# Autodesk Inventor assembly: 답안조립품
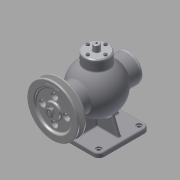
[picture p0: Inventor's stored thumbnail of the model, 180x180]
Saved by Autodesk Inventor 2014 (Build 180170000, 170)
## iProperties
Created: 2015-10
Part Number: 답안조립품
Document SubType Name: Assembly
Designer: youjin13
Author: youjin13
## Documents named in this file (19)
- C:\Users\youjin13\Desktop\451010V1009\답안조립품.iam
- C:\Users\youjin13\Desktop\451010V1009\본체.ipt
- C:\Users\youjin13\Desktop\451010V1009\뒤커버.ipt
- C:\Users\youjin13\Desktop\451010V1009\앞커버.ipt
- C:\Users\youjin13\Desktop\451010V1009\상부커버.ipt
- C:\Users\youjin13\Desktop\451010V1009\오일실 15 30 7.ipt
- C:\Users\youjin13\Desktop\451010V1009\볼트 M4 x 16.ipt
- C:\Users\youjin13\Desktop\451010V1009\볼트 M 4 x 12.ipt
- C:\Users\youjin13\Desktop\451010V1009\베어링- 6202.ipt
- KS B 2023 - 6202 - 15 x 35 x 11 - 7.8.ipt
- C:\Users\youjin13\Desktop\451010V1009\편심축.ipt
- C:\Users\youjin13\Desktop\451010V1009\부시.ipt
- C:\Users\youjin13\Desktop\451010V1009\키 4 x 4 x 12.ipt
- C:\Users\youjin13\Desktop\451010V1009\멈춤링- 35x1.6.ipt
- KS B 1336 - 35x1.6.ipt
- C:\Users\youjin13\Desktop\451010V1009\멈춤링- 15 x 1.ipt
- C:\Users\youjin13\Desktop\451010V1009\V-벨트풀리.ipt
- C:\Users\youjin13\Desktop\451010V1009\너트 M8.ipt
- C:\Users\youjin13\Desktop\451010V1009\슬라이드.ipt
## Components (16 placed, 5 different names)
1. KS B 2023 - 6202 - 15 x 35 x 11 - 7.8:1 — Mate:14, Mate:15, Mate:31, Mate:32, Mate:33, Angle:1
2. KS B 2023 - 6202 - 15 x 35 x 11 - 7.8:2 — Mate:12, Mate:13, Mate:16, Mate:25, Angle:2
3. KS B 1336 - 35x1.6:1 — Mate:31, Mate:32, Angle:4
4. V-벨트풀리:1 — Mate:35, Flush:1, Mate:36
5. ISO 4762 M4 x 16:1 — Insert:1
6. ISO 4762 M4 x 16:3
7. ISO 4762 M4 x 16:4
8. ISO 4762 M4 x 16:5
9. ISO 4762 M4 x 16:2 — Insert:2
10. ISO 4762 M4 x 16:6
11. ISO 4762 M4 x 16:7
12. ISO 4762 M4 x 16:8
13. KS B 1021 - 에 따름 ISO 1207 - 미터 A  M 4 x 12:1 — Insert:3
14. KS B 1021 - 에 따름 ISO 1207 - 미터 A  M 4 x 12:2
15. KS B 1021 - 에 따름 ISO 1207 - 미터 A  M 4 x 12:3
16. KS B 1021 - 에 따름 ISO 1207 - 미터 A  M 4 x 12:4
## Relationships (18: Mate 11, Insert 3, Angle 3, Flush 1)
- Insert:1: ISO 4762 M4 x 16:1
- Insert:2: ISO 4762 M4 x 16:2
- Insert:3: KS B 1021 - 에 따름 ISO 1207 - 미터 A  M 4 x 12:1
- Mate:12: KS B 2023 - 6202 - 15 x 35 x 11 - 7.8:2
- Mate:13: KS B 2023 - 6202 - 15 x 35 x 11 - 7.8:2
- Mate:14: KS B 2023 - 6202 - 15 x 35 x 11 - 7.8:1
- Mate:15: KS B 2023 - 6202 - 15 x 35 x 11 - 7.8:1
- Mate:16: KS B 2023 - 6202 - 15 x 35 x 11 - 7.8:2
- Mate:25: KS B 2023 - 6202 - 15 x 35 x 11 - 7.8:2
- Mate:31: KS B 2023 - 6202 - 15 x 35 x 11 - 7.8:1 ↔ KS B 1336 - 35x1.6:1
- Mate:32: KS B 2023 - 6202 - 15 x 35 x 11 - 7.8:1 ↔ KS B 1336 - 35x1.6:1
- Mate:33: KS B 2023 - 6202 - 15 x 35 x 11 - 7.8:1
- Mate:35: V-벨트풀리:1
- Flush:1: V-벨트풀리:1
- Mate:36: V-벨트풀리:1
- Angle:1: KS B 2023 - 6202 - 15 x 35 x 11 - 7.8:1
- Angle:2: KS B 2023 - 6202 - 15 x 35 x 11 - 7.8:2
- Angle:4: KS B 1336 - 35x1.6:1
